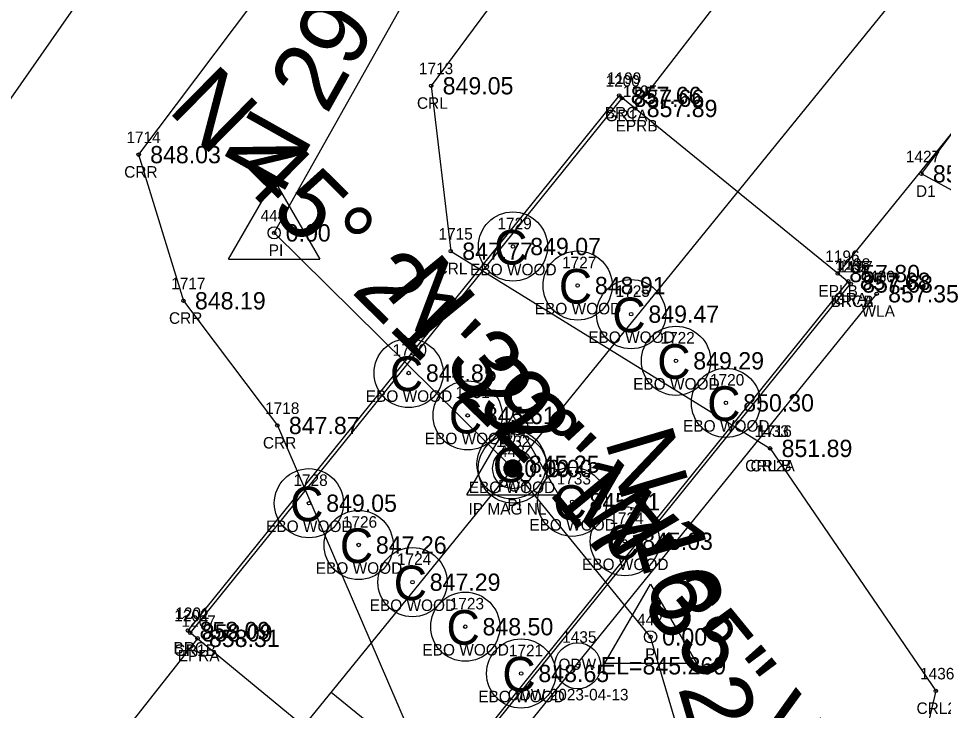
# Model space of a CAD drawing. Extents: x 1448136 to 1453623, y 1125056 to 1128842.
# Drawn here: x 1450680.5 to 1450760.7, y 1126932.5 to 1126992.5 of the extents above; entities that cross this region are included whole.
import ezdxf

# ---------------------------------------------------------------- set-up
doc = ezdxf.new("R2010")
doc.units = 0
for name, color, linetype in [('RD_EX_Bridge', 7, 'Continuous'), ('RD_EX_Bridge_txCode', 7, 'Continuous'), ('RD_EX_Driveway', 7, 'Continuous'), ('RD_EX_Driveway_txCode', 7, 'Continuous'), ('RD_EX_DV_Prop_txCode', 7, 'Continuous'), ('RD_EX_DV_PropPin', 7, 'Continuous'), ('RD_EX_GuardRail', 7, 'Continuous'), ('RD_EX_GuardRail_txCode', 7, 'Continuous'), ('RD_EX_H2O', 7, 'Continuous'), ('RD_EX_H2O_txCode', 7, 'Continuous'), ('RD_EX_Road', 7, 'Continuous'), ('RD_EX_Road_txCode', 7, 'Continuous'), ('RD_EX_TX_Bridge_ELEV', 7, 'Continuous'), ('RD_EX_TX_Driveway_ELEV', 7, 'Continuous'), ('RD_EX_TX_DV_Prop_ELEV', 7, 'Continuous'), ('RD_EX_TX_GuardRail_ELEV', 7, 'Continuous'), ('RD_EX_TX_H2O_ELEV', 7, 'Continuous'), ('RD_EX_TX_Road_ELEV', 7, 'Continuous'), ('RD_EX_TX_UT_ELEV', 7, 'Continuous'), ('RD_EX_UT', 7, 'Continuous'), ('RD_EX_UT_txCode', 7, 'Continuous'), ('RD_EX_VEG', 7, 'Continuous'), ('RD_HC_Cl', 7, 'Continuous'), ('RD_HC_Data', 7, 'Continuous'), ('RD_HC_Data_Tic', 7, 'Continuous'), ('RD_HC_Survey_ELEV', 7, 'Continuous'), ('RD_HC_txCode', 7, 'Continuous'), ('RD_SMD_Locator', 7, 'Continuous')]:
    doc.layers.add(name, color=color, linetype=linetype)

msp = doc.modelspace()

# ---------------------------------------------------------------- linework, layer by layer
at = {"layer": 'RD_EX_Bridge'}
msp.add_lwpolyline([(1450752.682, 1126969.491), (1450732.61, 1126985.852), (1450695.205, 1126939.422), (1450715.121, 1126922.991), (1450752.682, 1126969.491)], dxfattribs=at)
for centre in [(1450723.392, 1126972.744), (1450728.999, 1126969.356), (1450733.642, 1126966.875), (1450737.534, 1126962.827), (1450714.343, 1126961.765), (1450741.866, 1126959.177), (1450719.46, 1126958.088), (1450723.272, 1126953.848), (1450705.694, 1126950.469), (1450728.53, 1126950.594), (1450710.005, 1126946.846), (1450733.1, 1126947.169), (1450714.676, 1126943.618), (1450719.256, 1126939.755), (1450724.101, 1126935.697)]:
    msp.add_circle(centre, 3, dxfattribs=at)
at = {"layer": 'RD_EX_Driveway'}
msp.add_lwpolyline([(1450755.319, 1126870.088), (1450756.908, 1126904.63), (1450765.178, 1126943.07), (1450766.814, 1126971.057), (1450764.578, 1126975.925), (1450758.819, 1126979.051), (1450762.34, 1126983.686)], dxfattribs=at)
at = {"layer": 'RD_EX_DV_PropPin'}
for p, q in [((1450722.642, 1126953.286), (1450722.642, 1126953.679)), ((1450722.677, 1126953.185), (1450722.677, 1126953.78)), ((1450722.712, 1126953.113), (1450722.712, 1126953.852)), ((1450722.747, 1126953.056), (1450722.747, 1126953.909)), ((1450722.782, 1126953.008), (1450722.782, 1126953.957)), ((1450722.817, 1126952.967), (1450722.817, 1126953.998)), ((1450722.852, 1126952.932), (1450722.852, 1126954.033)), ((1450722.887, 1126952.9), (1450722.887, 1126954.065)), ((1450722.922, 1126952.873), (1450722.922, 1126954.092)), ((1450722.957, 1126952.848), (1450722.957, 1126954.117)), ((1450722.992, 1126952.826), (1450722.992, 1126954.139)), ((1450723.027, 1126952.807), (1450723.027, 1126954.158)), ((1450723.062, 1126952.79), (1450723.062, 1126954.175)), ((1450723.097, 1126952.775), (1450723.097, 1126954.19)), ((1450723.132, 1126952.762), (1450723.132, 1126954.203)), ((1450723.167, 1126952.751), (1450723.167, 1126954.214)), ((1450723.202, 1126952.742), (1450723.202, 1126954.223)), ((1450723.237, 1126952.734), (1450723.237, 1126954.231)), ((1450723.272, 1126952.729), (1450723.272, 1126954.236)), ((1450723.307, 1126952.725), (1450723.307, 1126954.24)), ((1450723.342, 1126952.722), (1450723.342, 1126954.243)), ((1450723.377, 1126952.721), (1450723.377, 1126954.244)), ((1450723.412, 1126952.722), (1450723.412, 1126954.243)), ((1450723.447, 1126952.725), (1450723.447, 1126954.24)), ((1450723.482, 1126952.729), (1450723.482, 1126954.236)), ((1450723.517, 1126952.734), (1450723.517, 1126954.231)), ((1450723.552, 1126952.742), (1450723.552, 1126954.223)), ((1450723.587, 1126952.751), (1450723.587, 1126954.214)), ((1450723.622, 1126952.762), (1450723.622, 1126954.203)), ((1450723.657, 1126952.775), (1450723.657, 1126954.19)), ((1450723.692, 1126952.79), (1450723.692, 1126954.175)), ((1450723.727, 1126952.807), (1450723.727, 1126954.158)), ((1450723.762, 1126952.826), (1450723.762, 1126954.139)), ((1450723.797, 1126952.848), (1450723.797, 1126954.117)), ((1450723.832, 1126952.873), (1450723.832, 1126954.092)), ((1450723.867, 1126952.9), (1450723.867, 1126954.065)), ((1450723.902, 1126952.932), (1450723.902, 1126954.033)), ((1450723.937, 1126952.967), (1450723.937, 1126953.998)), ((1450723.972, 1126953.008), (1450723.972, 1126953.957)), ((1450724.007, 1126953.056), (1450724.007, 1126953.909)), ((1450724.042, 1126953.113), (1450724.042, 1126953.852)), ((1450724.077, 1126953.185), (1450724.077, 1126953.78)), ((1450724.112, 1126953.286), (1450724.112, 1126953.679))]:
    msp.add_line(p, q, dxfattribs=at)
for radius in [1.75, 0.761]:
    msp.add_circle((1450723.377, 1126953.482), radius, dxfattribs=at)
at = {"layer": 'RD_EX_GuardRail'}
for p, q in [((1450732.85, 1126985.611), (1450695.399, 1126939.22)), ((1450752.477, 1126969.723), (1450714.894, 1126923.178))]:
    msp.add_line(p, q, dxfattribs=at)
at = {"layer": 'RD_EX_H2O'}
for points in [[(1450790.266, 1127617.477), (1450787.405, 1127572.488), (1450770.56, 1127562.94), (1450759.958, 1127503.293), (1450769.343, 1127461.296), (1450745.953, 1127442.744), (1450719.185, 1127377.134), (1450706.091, 1127312.949), (1450685.565, 1127238.741), (1450684.415, 1127163.983), (1450689.617, 1127099.648), (1450700.631, 1127049.817), (1450721.694, 1127031.115), (1450714.056, 1127011.463), (1450690.923, 1126980.716), (1450694.809, 1126968.037), (1450702.956, 1126957.215), (1450718.262, 1126921.701)], [(1451186.933, 1127499.899), (1451179.17, 1127493.969), (1451140.725, 1127490.624), (1451106.634, 1127492.288), (1451048.454, 1127510.078), (1451003.538, 1127518.512), (1450913.117, 1127519.758), (1450847.922, 1127518.314), (1450803.268, 1127536.045), (1450784.136, 1127535.395), (1450799.356, 1127449.253), (1450771.539, 1127417.413), (1450741.813, 1127369.626), (1450735.367, 1127299.023), (1450712.284, 1127225.281), (1450704.175, 1127161.12), (1450710.832, 1127118.365), (1450722.873, 1127082.489), (1450720.786, 1127059.542), (1450742.042, 1127027.9), (1450729.122, 1127004.034), (1450716.297, 1126986.691), (1450717.995, 1126972.338), (1450745.696, 1126955.228)], [(1450745.696, 1126955.228), (1450760.074, 1126934.183), (1450752.702, 1126902.942), (1450751.991, 1126845.751), (1450749.838, 1126753.839), (1450765.552, 1126601.502), (1450766.355, 1126534.456), (1450772.788, 1126478.952), (1450780.128, 1126423.057)]]:
    msp.add_lwpolyline(points, dxfattribs=at)
for radius in [2, 0.15]:
    msp.add_circle((1450729.007, 1126936.362), radius, dxfattribs=at)
at = {"layer": 'RD_EX_Road'}
for points in [[(1450902.689, 1127193.099), (1450871.018, 1127154.79), (1450870.722, 1127154.625), (1450839.396, 1127115.964), (1450808.223, 1127077.268), (1450776.52, 1127037.706), (1450745.448, 1126999.567), (1450733.996, 1126984.723)], [(1450889.116, 1127140.054), (1450857.394, 1127100.421), (1450825.548, 1127060.756), (1450804.119, 1127034.173), (1450797.398, 1127023.382), (1450762.34, 1126983.686), (1450751.567, 1126970.399)], [(1450696.026, 1126938.745), (1450682.061, 1126921.003), (1450652.28, 1126884.75), (1450619.837, 1126847.491), (1450585.671, 1126813.189), (1450567.697, 1126796.905), (1450549.636, 1126781.657), (1450510.035, 1126752.98), (1450468.429, 1126728.625), (1450425.524, 1126707.881), (1450379.552, 1126690.085), (1450334.806, 1126677.215), (1450288.338, 1126667.766)]]:
    msp.add_lwpolyline(points, dxfattribs=at)
at = {"layer": 'RD_EX_UT'}
msp.add_line((1450754.936, 1126968.645), (1450715.739, 1126920.227), dxfattribs=at)
at = {"layer": 'RD_EX_VEG'}
msp.add_lwpolyline([(1450701.325, 1127016.456), (1450648.976, 1126941.431), (1450624.046, 1126912.283), (1450597.045, 1126871.161), (1450572.198, 1126846.226), (1450510.88, 1126885.489)], dxfattribs=at)
at = {"layer": 'RD_HC_Cl'}
for p, q in [((1450930.039, 1127207.931), (1450648.853, 1126861.726)), ((1450702.679, 1126973.925), (1450733.129, 1127028.192)), ((1450723.377, 1126953.482), (1450702.679, 1126973.925)), ((1450735.332, 1126938.873), (1450723.377, 1126953.482)), ((1450739.888, 1126923.462), (1450735.332, 1126938.873))]:
    msp.add_line(p, q, dxfattribs=at)
at = {"layer": 'RD_HC_Data'}
for p, q in [((1450698.708, 1126971.632), (1450702.68, 1126978.512)), ((1450702.68, 1126978.512), (1450706.649, 1126971.632)), ((1450698.708, 1126971.632), (1450706.649, 1126971.632)), ((1450719.406, 1126951.19), (1450723.378, 1126958.069)), ((1450723.378, 1126958.069), (1450727.347, 1126951.19)), ((1450719.406, 1126951.19), (1450727.347, 1126951.19)), ((1450731.361, 1126936.58), (1450735.333, 1126943.46)), ((1450735.333, 1126943.46), (1450739.302, 1126936.58)), ((1450731.361, 1126936.58), (1450739.302, 1126936.58))]:
    msp.add_line(p, q, dxfattribs=at)
for centre, radius in [((1450702.679, 1126973.925), 0.529), ((1450723.377, 1126953.483), 3), ((1450723.377, 1126953.482), 0.529), ((1450723.377, 1126953.482), 0.282), ((1450735.332, 1126938.873), 0.529)]:
    msp.add_circle(centre, radius, dxfattribs=at)
at = {"layer": 'RD_HC_Data_Tic'}
msp.add_line((1450707.617, 1126934.078), (1450710.722, 1126931.556), dxfattribs=at)
at = {"layer": 'RD_SMD_Locator'}
for centre in [(1450716.297, 1126986.691), (1450732.61, 1126985.852), (1450732.85, 1126985.611), (1450733.996, 1126984.723), (1450690.923, 1126980.716), (1450758.819, 1126979.051), (1450702.679, 1126973.925), (1450723.392, 1126972.744), (1450717.995, 1126972.338), (1450751.567, 1126970.399), (1450752.477, 1126969.723), (1450728.999, 1126969.356), (1450752.682, 1126969.491), (1450752.682, 1126969.491), (1450694.809, 1126968.037), (1450754.936, 1126968.645), (1450733.642, 1126966.875), (1450737.534, 1126962.827), (1450714.343, 1126961.765), (1450741.866, 1126959.177), (1450719.461, 1126958.088), (1450702.956, 1126957.215), (1450745.696, 1126955.228), (1450745.696, 1126955.228), (1450723.272, 1126953.848), (1450723.377, 1126953.482), (1450723.377, 1126953.482), (1450723.377, 1126953.482), (1450705.694, 1126950.469), (1450728.53, 1126950.594), (1450733.1, 1126947.169), (1450710.005, 1126946.846), (1450714.676, 1126943.618), (1450695.205, 1126939.422), (1450695.399, 1126939.22), (1450719.256, 1126939.755), (1450696.026, 1126938.745), (1450735.332, 1126938.873), (1450724.101, 1126935.697), (1450760.074, 1126934.183)]:
    msp.add_circle(centre, 0.15, dxfattribs=at)

# ---------------------------------------------------------------- texts
at = {"layer": 'RD_EX_Bridge'}
for p in [(1450721.761, 1126971.182), (1450727.369, 1126967.794), (1450732.011, 1126965.314), (1450735.903, 1126961.265), (1450712.712, 1126960.203), (1450740.236, 1126957.615), (1450717.83, 1126956.527), (1450721.641, 1126952.287), (1450726.899, 1126949.032), (1450704.063, 1126948.908), (1450708.374, 1126945.285), (1450731.469, 1126945.608), (1450713.046, 1126942.057), (1450717.625, 1126938.193), (1450722.47, 1126934.136)]:
    msp.add_text('C', height=3, dxfattribs=at).set_placement(p)
at = {"layer": 'RD_EX_Bridge_txCode'}
for s, p in [('1199', (1450731.547, 1126986.852)), ('BRC', (1450731.358, 1126983.852)), ('1729', (1450722.046, 1126974.244)), ('1727', (1450727.653, 1126970.856)), ('1205', (1450751.296, 1126970.491)), ('1197', (1450751.619, 1126970.491)), ('EBO WOOD', (1450719.675, 1126970.244)), ('1725', (1450732.296, 1126968.375)), ('BRCA', (1450750.942, 1126967.491)), ('BRCB', (1450750.958, 1126967.491)), ('EBO WOOD', (1450725.283, 1126966.856)), ('EBO WOOD', (1450729.926, 1126964.375)), ('1722', (1450736.188, 1126964.327)), ('1730', (1450712.957, 1126963.265)), ('1720', (1450740.481, 1126960.677)), ('EBO WOOD', (1450733.818, 1126960.327)), ('EBO WOOD', (1450710.626, 1126959.265)), ('1731', (1450718.398, 1126959.588)), ('EBO WOOD', (1450738.15, 1126956.677)), ('EBO WOOD', (1450715.744, 1126955.588)), ('1732', (1450721.926, 1126955.348)), ('1728', (1450704.347, 1126951.969)), ('1733', (1450727.184, 1126952.094)), ('EBO WOOD', (1450719.556, 1126951.348)), ('1734', (1450731.754, 1126948.669)), ('EBO WOOD', (1450701.977, 1126947.969)), ('1726', (1450708.635, 1126948.346)), ('EBO WOOD', (1450724.813, 1126948.094)), ('1724', (1450713.33, 1126945.118)), ('EBO WOOD', (1450729.383, 1126944.669)), ('EBO WOOD', (1450706.288, 1126944.346)), ('EBO WOOD', (1450710.96, 1126941.118)), ('1723', (1450717.909, 1126941.255)), ('1201', (1450694.103, 1126940.422)), ('BRC', (1450693.953, 1126937.422)), ('EBO WOOD', (1450715.539, 1126937.255)), ('1721', (1450723.038, 1126937.197)), ('EBO WOOD', (1450720.384, 1126933.197))]:
    msp.add_text(s, height=1, dxfattribs=at).set_placement(p)
at = {"layer": 'RD_EX_Driveway_txCode'}
for s, p in [('1427', (1450757.473, 1126980.051)), ('D1', (1450758.347, 1126977.051))]:
    msp.add_text(s, height=1, dxfattribs=at).set_placement(p)
at = {"layer": 'RD_EX_DV_Prop_txCode'}
for s, p in [('1015', (1450722.275, 1126956.483)), ('IP MAG NL', (1450719.542, 1126949.483))]:
    msp.add_text(s, height=1, dxfattribs=at).set_placement(p)
at = {"layer": 'RD_EX_GuardRail_txCode'}
for s, p in [('1200', (1450731.424, 1126986.611)), ('GR1A', (1450731.416, 1126983.611)), ('1198', (1450751.414, 1126970.723)), ('GRA', (1450751.209, 1126967.723)), ('1202', (1450694.013, 1126940.22)), ('GR1B', (1450693.981, 1126937.22))]:
    msp.add_text(s, height=1, dxfattribs=at).set_placement(p)
at = {"layer": 'RD_EX_H2O'}
msp.add_text('ODW', height=1, dxfattribs=at).set_placement((1450727.34, 1126935.987))
at = {"layer": 'RD_EX_H2O_txCode'}
for s, p in [('1713', (1450715.234, 1126987.691)), ('CRL', (1450715.068, 1126984.691)), ('1714', (1450689.86, 1126981.716)), ('CRR', (1450689.671, 1126978.716)), ('1715', (1450716.932, 1126973.338)), ('CRL', (1450716.767, 1126970.338)), ('1717', (1450693.746, 1126969.037)), ('CRR', (1450693.557, 1126966.037)), ('1718', (1450701.893, 1126958.215)), ('1433', (1450744.349, 1126956.228)), ('1716', (1450744.609, 1126956.228)), ('CRR', (1450701.704, 1126955.215)), ('CRL2A', (1450743.53, 1126953.228)), ('CRLB', (1450743.995, 1126953.228)), ('1435', (1450727.66, 1126938.362)), ('1436', (1450758.704, 1126935.183)), ('ODW 2023-04-13', (1450722.936, 1126933.362)), ('CRL2', (1450758.397, 1126932.183))]:
    msp.add_text(s, height=1, dxfattribs=at).set_placement(p)
at = {"layer": 'RD_EX_Road_txCode'}
for s, p in [('1195', (1450732.933, 1126985.723)), ('EPRB', (1450732.295, 1126982.723)), ('1196', (1450750.481, 1126971.399)), ('EPLB', (1450749.89, 1126968.399)), ('1207', (1450694.64, 1126939.745)), ('EPRA', (1450694.309, 1126936.745))]:
    msp.add_text(s, height=1, dxfattribs=at).set_placement(p)
at = {"layer": 'RD_EX_TX_Bridge_ELEV'}
for s, p in [('857.66', (1450733.61, 1126985.102)), ('849.07', (1450724.892, 1126971.994)), ('848.91', (1450730.499, 1126968.606)), ('857.68', (1450753.682, 1126968.741)), ('857.68', (1450753.682, 1126968.741)), ('849.47', (1450735.142, 1126966.125)), ('849.29', (1450739.034, 1126962.077)), ('844.85', (1450715.843, 1126961.015)), ('850.30', (1450743.366, 1126958.427)), ('845.61', (1450720.961, 1126957.338)), ('845.25', (1450724.772, 1126953.098)), ('849.05', (1450707.194, 1126949.719)), ('845.51', (1450730.03, 1126949.844)), ('847.26', (1450711.505, 1126946.096)), ('845.03', (1450734.6, 1126946.419)), ('847.29', (1450716.176, 1126942.868)), ('858.09', (1450696.205, 1126938.672)), ('848.50', (1450720.756, 1126939.005)), ('848.65', (1450725.601, 1126934.947))]:
    msp.add_text(s, height=1.5, dxfattribs=at).set_placement(p)
at = {"layer": 'RD_EX_TX_Driveway_ELEV'}
msp.add_text('857.86', height=1.5, dxfattribs=at).set_placement((1450759.819, 1126978.301))
at = {"layer": 'RD_EX_TX_DV_Prop_ELEV'}
msp.add_text('0.00', height=1.5, dxfattribs=at).set_placement((1450726.377, 1126952.733))
at = {"layer": 'RD_EX_TX_GuardRail_ELEV'}
for s, p in [('857.66', (1450733.85, 1126984.861)), ('857.68', (1450753.477, 1126968.973)), ('858.09', (1450696.399, 1126938.47))]:
    msp.add_text(s, height=1.5, dxfattribs=at).set_placement(p)
at = {"layer": 'RD_EX_TX_H2O_ELEV'}
for s, p in [('849.05', (1450717.297, 1126985.941)), ('848.03', (1450691.923, 1126979.966)), ('847.77', (1450718.995, 1126971.588)), ('848.19', (1450695.809, 1126967.287)), ('847.87', (1450703.956, 1126956.465)), ('851.89', (1450746.696, 1126954.478)), ('851.89', (1450746.696, 1126954.478)), ('EL=845.269', (1450731.007, 1126935.612))]:
    msp.add_text(s, height=1.5, dxfattribs=at).set_placement(p)
at = {"layer": 'RD_EX_TX_Road_ELEV'}
for s, p in [('857.89', (1450734.996, 1126983.973)), ('857.80', (1450752.567, 1126969.649)), ('858.31', (1450697.026, 1126937.995))]:
    msp.add_text(s, height=1.5, dxfattribs=at).set_placement(p)
at = {"layer": 'RD_EX_TX_UT_ELEV'}
msp.add_text('857.35', height=1.5, dxfattribs=at).set_placement((1450755.936, 1126967.895))
at = {"layer": 'RD_EX_UT_txCode'}
for s, p in [('1430', (1450753.55, 1126969.645)), ('WLA', (1450753.629, 1126966.645))]:
    msp.add_text(s, height=1, dxfattribs=at).set_placement(p)
at = {"layer": 'RD_HC_Data'}
for s, rotation, p in [('N 29%%d 17\' 50" E', 60.70285, (1450703.311, 1126977.095)), ('N 45%%d 21\' 22" W', 315.35611, (1450693.344, 1126984.55)), ('N 39%%d 17\' 35" W', 309.29306, (1450712.192, 1126968.731)), ('N 16%%d 28\' 11" W', 286.46986, (1450731.329, 1126955.939))]:
    msp.add_text(s, height=6, rotation=rotation, dxfattribs=at).set_placement(p)
at = {"layer": 'RD_HC_Survey_ELEV'}
for p in [(1450703.679, 1126973.175), (1450724.377, 1126952.733), (1450724.377, 1126952.733), (1450736.332, 1126938.123)]:
    msp.add_text('0.00', height=1.5, dxfattribs=at).set_placement(p)
at = {"layer": 'RD_HC_txCode'}
for s, p in [('444', (1450701.498, 1126974.925)), ('PI', (1450702.207, 1126971.925)), ('407', (1450722.157, 1126955.681)), ('443', (1450722.196, 1126954.483)), ('POT', (1450722.094, 1126951.483)), ('PI', (1450722.905, 1126949.841)), ('442', (1450734.151, 1126939.873)), ('PI', (1450734.859, 1126936.873))]:
    msp.add_text(s, height=1, dxfattribs=at).set_placement(p)

doc.saveas('drawing.dxf')
